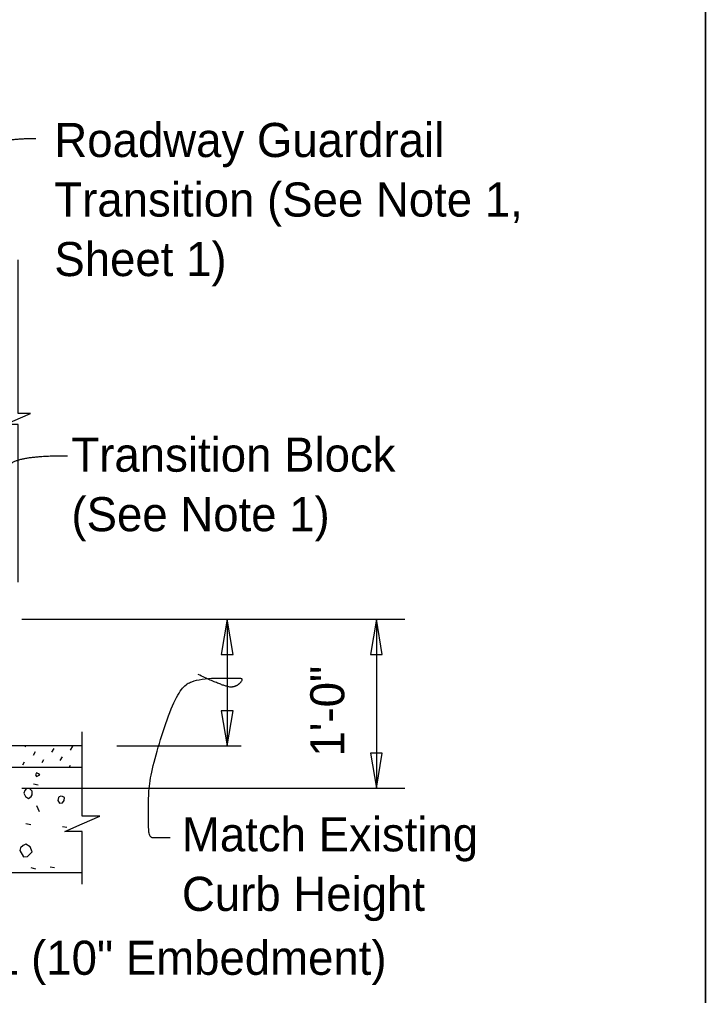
# Model space of a CAD drawing. Extents: x 0 to 41.1, y 0 to 25.9.
# Drawn here: x 36.99 to 41.05, y 5.23 to 11.01 of the extents above; entities that cross this region are included whole.
import ezdxf

# ---------------------------------------------------------------- set-up
doc = ezdxf.new("R2010")
doc.units = 0
for name, color, linetype in [('Dimension', 7, 'Continuous'), ('ExistSuperStruct', 7, 'Continuous'), ('Miscellaneous', 7, 'Continuous'), ('Miscellaneous1', 7, 'Continuous'), ('TextStructures', 7, 'Continuous')]:
    doc.layers.add(name, color=color, linetype=linetype)

msp = doc.modelspace()

# ---------------------------------------------------------------- linework, layer by layer
at = {"layer": 'Dimension'}
for p, q in [((37.0058, 7.4599), (39.2714, 7.4599)), ((38.2207, 7.4599), (38.2207, 6.7099)), ((39.1029, 7.46), (39.1029, 6.46)), ((37.568, 6.7099), (38.3034, 6.7099)), ((37.0058, 6.4599), (39.2714, 6.4599))]:
    msp.add_line(p, q, dxfattribs=at)
for points in [[(36.9839, 7.6788), (36.9839, 8.6104), (36.9064, 8.6104), (37.0564, 8.6766), (36.9839, 8.6766), (36.9839, 9.5855)], [(37.3622, 5.892), (37.3622, 6.2045), (37.2589, 6.2045), (37.3622, 6.2495), (37.4655, 6.2945), (37.3622, 6.2945), (37.3622, 6.7942)]]:
    msp.add_lwpolyline(points, dxfattribs=at)
for points in [[(38.2207, 7.4599), (38.1854, 7.2516), (38.256, 7.2516)], [(39.1028, 7.46), (39.0676, 7.2517), (39.1381, 7.2517)], [(38.2207, 6.7099), (38.256, 6.9181), (38.1854, 6.9181)], [(39.1028, 6.46), (39.1381, 6.6682), (39.0676, 6.6682)]]:
    msp.add_lwpolyline(points, close=True, dxfattribs=at)
for points in [[(37.0881, 10.3011), (36.8373, 10.3011), (36.3859, 10.1306), (35.9697, 9.9149), (35.5032, 9.4435)], [(37.2746, 8.4245), (37.0591, 8.4245), (36.8965, 8.3714), (36.6668, 8.0709), (36.43, 7.4629)], [(37.8825, 6.1672), (37.8047, 6.1672), (37.7553, 6.1672), (37.7553, 6.2874), (37.7553, 6.5313), (37.9249, 7.0546), (38.0592, 7.1111), (38.2606, 7.1111), (38.3207, 7.1111), (38.2748, 7.0581), (38.2076, 7.0581), (38.0486, 7.1323)]]:
    msp.add_open_spline(points, degree=2, dxfattribs=at)
at = {"layer": 'ExistSuperStruct'}
for p, q in [((37.3622, 6.71), (26.6139, 6.71)), ((26.6139, 6.585), (37.3622, 6.585)), ((37.3622, 5.9599), (31.8338, 5.9599))]:
    msp.add_line(p, q, dxfattribs=at)
at = {"layer": 'Miscellaneous'}
for p, q in [((37.0248, 6.7046), (37.028, 6.71)), ((37.183, 6.6725), (37.196, 6.6949)), ((37.2936, 6.6855), (37.3066, 6.7079)), ((37.0736, 6.6557), (37.0866, 6.6781)), ((37.2318, 6.6237), (37.2448, 6.6461)), ((37.0117, 6.5982), (37.0216, 6.6153)), ((37.1255, 6.6122), (37.1354, 6.6293)), ((37.1823, 6.5832), (37.183, 6.5843)), ((37.2855, 6.5832), (37.2936, 6.5973)), ((37.0737, 6.4866), (37.102, 6.4795)), ((37.1086, 6.3214), (37.0945, 6.3567)), ((37.0292, 6.2522), (37.0574, 6.2451)), ((37.2465, 6.233), (37.2712, 6.2294)), ((37.0572, 5.9914), (37.0855, 5.9843)), ((37.1722, 5.9961), (37.1988, 5.9908))]:
    msp.add_line(p, q, dxfattribs=at)
for points in [[(37.0917, 6.5297), (37.1112, 6.5385), (37.1041, 6.5456), (37.0917, 6.5509), (37.0864, 6.5385), (37.0917, 6.5297)], [(37.0169, 6.4317), (37.0275, 6.4105), (37.0452, 6.3999), (37.0593, 6.4105), (37.0664, 6.4211), (37.0664, 6.4423), (37.0505, 6.4582), (37.0311, 6.4564), (37.0222, 6.4476), (37.0169, 6.4317)], [(37.2182, 6.3885), (37.227, 6.3726), (37.2465, 6.3744), (37.2553, 6.3868), (37.2571, 6.4062), (37.2447, 6.4115), (37.2359, 6.4133), (37.2253, 6.4098), (37.2217, 6.4062), (37.2182, 6.3885)], [(36.9924, 6.0915), (37.0154, 6.0544), (37.0384, 6.0562), (37.0472, 6.065), (37.0666, 6.0845), (37.0543, 6.1145), (37.0295, 6.1287), (37.0118, 6.1216), (36.9977, 6.1075), (36.9924, 6.0915)]]:
    msp.add_lwpolyline(points, dxfattribs=at)
at = {"layer": 'Miscellaneous1'}
msp.add_lwpolyline([(0, 25.9461), (41.0506, 25.9461), (41.0506, 0), (0, 0)], close=True, dxfattribs=at)
at = {"layer": 'TextStructures'}
msp.add_lwpolyline([(0, 0), (41.0506, 0), (41.0506, 25.9461), (0, 25.9461)], close=True, dxfattribs=at)

# ---------------------------------------------------------------- texts
at = {"layer": 'Dimension'}
for s, p in [('Roadway Guardrail ', (37.1973, 10.1925)), ('Transition (See Note 1, ', (37.1973, 9.8405)), ('Sheet 1)', (37.1973, 9.4885)), ('Transition Block', (37.2984, 8.3318)), ('(See Note 1)', (37.2984, 7.9798)), ('Match Existing ', (37.9522, 6.0867)), ('Curb Height', (37.9522, 5.7347)), ('Dowel Bars 4L (10" Embedment) ', (35.2319, 5.3567))]:
    msp.add_text(s, height=0.2016, dxfattribs=at).set_placement(p)
at = {"layer": 'TextStructures'}
msp.add_text('1\'-0"', height=0.2016, rotation=90, dxfattribs=at).set_placement((38.9132, 6.6471))

doc.saveas('drawing.dxf')
